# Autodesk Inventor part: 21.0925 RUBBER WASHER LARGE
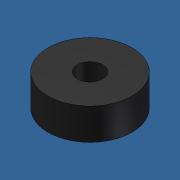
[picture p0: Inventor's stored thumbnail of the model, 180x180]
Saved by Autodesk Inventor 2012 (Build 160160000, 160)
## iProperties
Created: 2013-10
Part Number: 21.0925 RUBBER WASHER LARGE
Material: Rubber
Document SubType Name: Modeling
Designer: Admin
Density: 0.93 g/cm^3
Mass: 15.9524 g
Surface Area: 47.3752 cm^2
Volume: 17.1531 cm^3
Author: Admin
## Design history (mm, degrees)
sketch "Sketch1"
  geometry: C1 r 6 at (0, 0); C2 r 20 at (0, 0); 1 further point
  constraints: 2 centre point, 2 coincident
  dimensions: "d0" = 12 diameter of C1; "d1" = 40 diameter of C2
extrude "Extrusion1" new body sketch "Sketch1" distance "d2" = 15; taper "d3" = 0 deg
body "Solid1"
